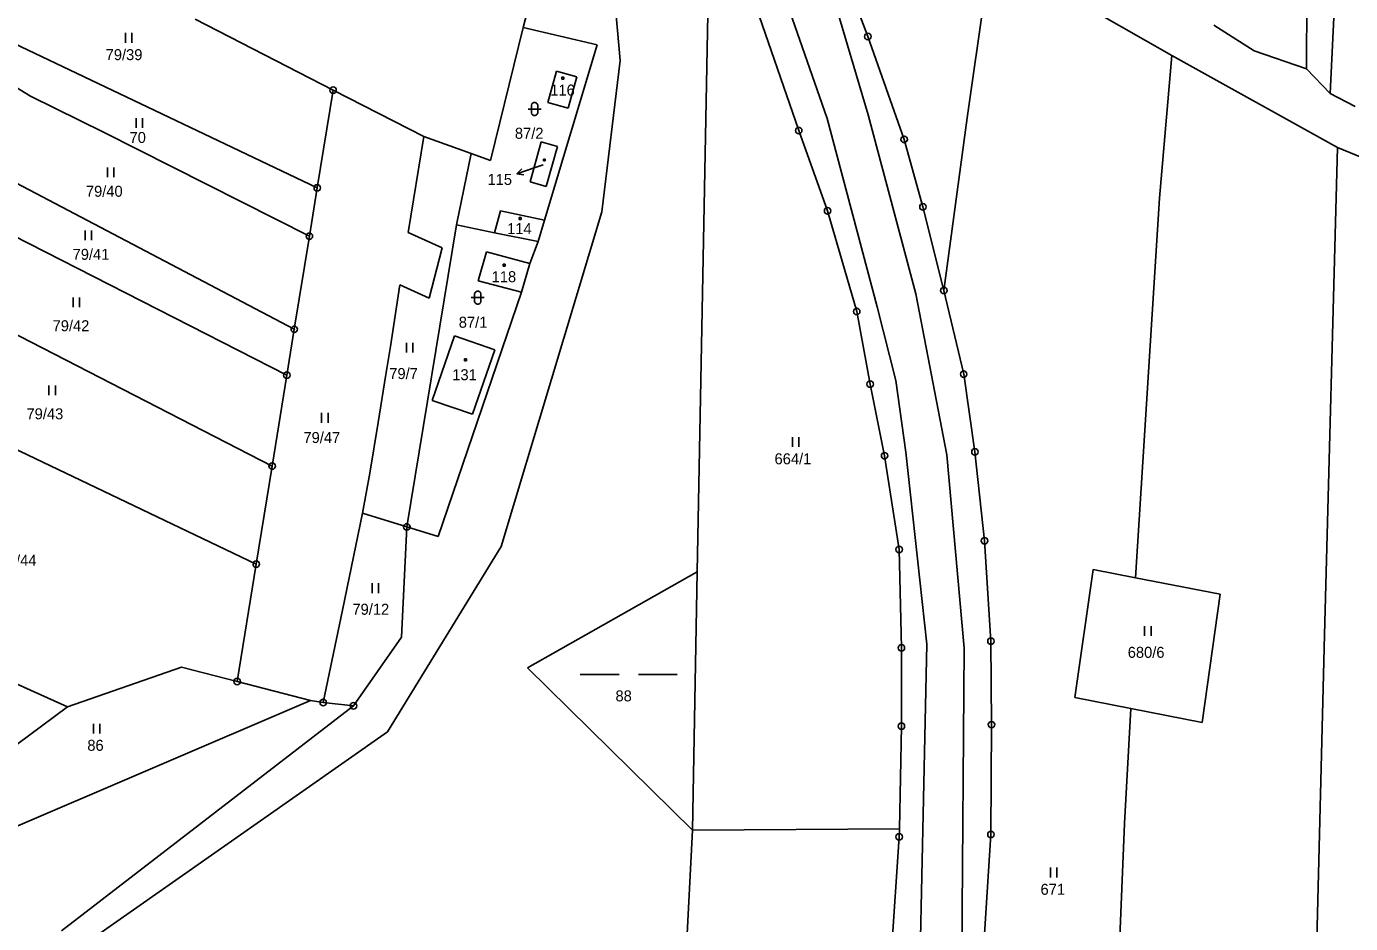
# Model space of a CAD drawing. Extents: x -794142 to -791199, y -1109267 to -1105626.
# Drawn here: x -793459.6 to -793254.8, y -1108185.5 to -1108046.6 of the extents above; entities that cross this region are included whole.
import ezdxf

# ---------------------------------------------------------------- set-up
doc = ezdxf.new("R2010")
doc.units = 0
for name, color, linetype in [('Komunikace', 7, 'Continuous'), ('Vrstva 1', 7, 'Continuous'), ('Vrstva 14', 7, 'Continuous'), ('Vrstva 15', 7, 'Continuous'), ('Vrstva 16', 7, 'Continuous'), ('Vrstva 2', 7, 'Continuous'), ('Vrstva 23', 7, 'Continuous'), ('Vrstva 25', 7, 'Continuous'), ('Vrstva 28', 7, 'Continuous')]:
    doc.layers.add(name, color=color, linetype=linetype)

msp = doc.modelspace()

# ---------------------------------------------------------------- linework, layer by layer
at = {"layer": 'Komunikace'}
msp.add_line((-793379.67, -1108068.04), (-793380.93, -1108068.48), dxfattribs=at)
at = {"layer": 'Vrstva 1'}
for p, q in [((-793257.94, -1108057.03), (-793255.37, -1108003.06)), ((-793261.46, -1108018.35), (-793261.6, -1108053.2)), ((-793353.85, -1108026.81), (-793355.86, -1108131.03)), ((-793367.78, -1108051.9), (-793369.41, -1108032.77)), ((-793310.44, -1108035.15), (-793314.07, -1108060.76)), ((-793282.44, -1108051.11), (-793310.44, -1108035.15)), ((-793332.85, -1108039.24), (-793329.45, -1108048.2)), ((-793381.6, -1108042.21), (-793382.75, -1108046.82)), ((-793479.51, -1108044.92), (-793458.99, -1108057.42)), ((-793433.49, -1108045.51), (-793412.17, -1108056.49)), ((-793346.28, -1108044.99), (-793340.14, -1108062.75)), ((-793387.84, -1108067.4), (-793382.75, -1108046.82)), ((-793371.31, -1108049.49), (-793382.75, -1108046.82)), ((-793329.45, -1108048.2), (-793323.82, -1108064.11)), ((-793275.93, -1108046.46), (-793269.7, -1108050.39)), ((-793462.7, -1108048.73), (-793414.62, -1108071.62)), ((-793379.44, -1108076.61), (-793371.31, -1108049.49)), ((-793269.7, -1108050.39), (-793261.6, -1108053.2)), ((-793370.62, -1108075.33), (-793367.78, -1108051.9)), ((-793284.33, -1108073.2), (-793282.44, -1108051.11)), ((-793282.44, -1108051.11), (-793256.81, -1108065.35)), ((-793377.6, -1108053.56), (-793378.95, -1108058.39)), ((-793377.6, -1108053.56), (-793374.46, -1108054.45)), ((-793374.46, -1108054.45), (-793375.82, -1108059.3)), ((-793261.6, -1108053.2), (-793257.94, -1108057.03)), ((-793412.17, -1108056.49), (-793414.62, -1108071.62)), ((-793412.17, -1108056.49), (-793398.15, -1108063.68)), ((-793458.99, -1108057.42), (-793447.57, -1108063.05)), ((-793375.82, -1108059.3), (-793378.95, -1108058.39)), ((-793257.94, -1108057.03), (-793254.06, -1108059.01)), ((-793481.29, -1108060.32), (-793418.17, -1108093.5)), ((-793314.07, -1108060.76), (-793317.69, -1108087.48)), ((-793447.57, -1108063.05), (-793415.84, -1108079.1)), ((-793400.56, -1108078.51), (-793398.15, -1108063.68)), ((-793398.15, -1108063.68), (-793390.82, -1108066.32)), ((-793379.96, -1108064.51), (-793381.66, -1108070.68)), ((-793379.96, -1108064.51), (-793377.47, -1108065.22)), ((-793340.14, -1108062.75), (-793335.67, -1108075.17)), ((-793323.82, -1108064.11), (-793320.92, -1108074.55)), ((-793393.1, -1108077.34), (-793390.82, -1108066.32)), ((-793390.82, -1108066.32), (-793387.84, -1108067.4)), ((-793377.47, -1108065.22), (-793379.21, -1108071.38)), ((-793256.81, -1108065.35), (-793258.79, -1108140.77)), ((-793256.81, -1108065.35), (-793242.18, -1108071.39)), ((-793419.32, -1108100.59), (-793482.23, -1108068.48)), ((-793379.21, -1108071.38), (-793381.66, -1108070.68)), ((-793414.62, -1108071.62), (-793415.84, -1108079.1)), ((-793320.92, -1108074.55), (-793317.69, -1108087.48)), ((-793288.02, -1108131.96), (-793284.33, -1108073.2)), ((-793386.26, -1108075.18), (-793387.18, -1108078.56)), ((-793379.44, -1108076.61), (-793386.26, -1108075.18)), ((-793386.16, -1108127.13), (-793370.62, -1108075.33)), ((-793380.44, -1108079.94), (-793379.44, -1108076.61)), ((-793335.67, -1108075.17), (-793331.17, -1108090.74)), ((-793400.77, -1108124.09), (-793393.1, -1108077.34)), ((-793395.3, -1108080.87), (-793400.56, -1108078.51)), ((-793387.18, -1108078.56), (-793393.1, -1108077.34)), ((-793380.44, -1108079.94), (-793387.18, -1108078.56)), ((-793415.84, -1108079.1), (-793418.17, -1108093.5)), ((-793397.32, -1108088.69), (-793395.3, -1108080.87)), ((-793381.74, -1108083.31), (-793380.44, -1108079.94)), ((-793388.43, -1108081.52), (-793389.72, -1108085.99)), ((-793381.74, -1108083.31), (-793388.43, -1108081.52)), ((-793381.74, -1108083.31), (-793383.03, -1108087.78)), ((-793403.3, -1108096.18), (-793401.87, -1108086.6)), ((-793401.87, -1108086.6), (-793397.32, -1108088.69)), ((-793383.03, -1108087.78), (-793389.72, -1108085.99)), ((-793383.03, -1108087.78), (-793395.93, -1108125.59)), ((-793317.69, -1108087.48), (-793314.62, -1108100.44)), ((-793421.6, -1108114.66), (-793468.95, -1108090.3)), ((-793331.17, -1108090.74), (-793329.09, -1108101.98)), ((-793418.17, -1108093.5), (-793419.32, -1108100.59)), ((-793393.4, -1108094.52), (-793396.84, -1108104.51)), ((-793387.17, -1108096.69), (-793393.4, -1108094.52)), ((-793404, -1108100.5), (-793403.3, -1108096.18)), ((-793390.58, -1108106.65), (-793387.17, -1108096.69)), ((-793419.32, -1108100.59), (-793421.6, -1108114.66)), ((-793404, -1108100.5), (-793405.2, -1108107.91)), ((-793314.62, -1108100.44), (-793312.88, -1108112.46)), ((-793329.09, -1108101.98), (-793326.85, -1108113.06)), ((-793396.84, -1108104.51), (-793390.58, -1108106.65)), ((-793470.04, -1108107.88), (-793424.06, -1108129.83)), ((-793405.2, -1108107.91), (-793406.48, -1108115.78)), ((-793326.85, -1108113.06), (-793324.6, -1108127.59)), ((-793312.88, -1108112.46), (-793311.39, -1108126.22)), ((-793421.6, -1108114.66), (-793424.06, -1108129.83)), ((-793407.6, -1108121.97), (-793406.48, -1108115.78)), ((-793410.71, -1108136.94), (-793407.6, -1108121.97)), ((-793407.6, -1108121.97), (-793400.77, -1108124.09)), ((-793400.77, -1108124.09), (-793401.61, -1108141.16)), ((-793400.77, -1108124.09), (-793395.93, -1108125.59)), ((-793403.74, -1108155.79), (-793386.16, -1108127.13)), ((-793324.6, -1108127.59), (-793324.25, -1108142.81)), ((-793311.39, -1108126.22), (-793310.4, -1108141.75)), ((-793424.06, -1108129.83), (-793427.01, -1108148)), ((-793355.86, -1108131.03), (-793382.1, -1108145.89)), ((-793356.57, -1108171.03), (-793355.86, -1108131.03)), ((-793294.61, -1108130.68), (-793297.41, -1108150.48)), ((-793294.61, -1108130.68), (-793288.02, -1108131.96)), ((-793288.02, -1108131.96), (-793274.95, -1108134.49)), ((-793453.28, -1108151.93), (-793494.33, -1108133.48)), ((-793274.95, -1108134.49), (-793277.71, -1108154.34)), ((-793413.69, -1108151.26), (-793410.71, -1108136.94)), ((-793401.61, -1108141.16), (-793409.01, -1108151.76)), ((-793310.4, -1108141.75), (-793310.32, -1108154.68)), ((-793258.79, -1108140.77), (-793261.5, -1108247.02)), ((-793324.25, -1108142.81), (-793324.25, -1108154.92)), ((-793435.62, -1108145.76), (-793453.28, -1108151.93)), ((-793427.01, -1108148), (-793435.62, -1108145.76)), ((-793382.1, -1108145.89), (-793356.57, -1108171.03)), ((-793415.67, -1108150.95), (-793427.01, -1108148)), ((-793297.41, -1108150.48), (-793288.76, -1108152.18)), ((-793480.52, -1108178.71), (-793415.67, -1108150.95)), ((-793453.28, -1108151.93), (-793463.11, -1108159.25)), ((-793454.16, -1108186.59), (-793409.01, -1108151.76)), ((-793415.67, -1108150.95), (-793413.69, -1108151.26)), ((-793409.01, -1108151.76), (-793413.69, -1108151.26)), ((-793289.76, -1108169.98), (-793288.76, -1108152.18)), ((-793288.76, -1108152.18), (-793277.71, -1108154.34)), ((-793310.32, -1108154.68), (-793310.4, -1108171.68)), ((-793450.61, -1108188.63), (-793403.74, -1108155.79)), ((-793324.25, -1108154.92), (-793324.57, -1108170.8)), ((-793356.57, -1108171.03), (-793362.45, -1108287.79)), ((-793356.57, -1108171.03), (-793324.57, -1108170.8)), ((-793324.57, -1108170.8), (-793324.6, -1108172.05)), ((-793291.8, -1108221.94), (-793289.76, -1108169.98)), ((-793324.6, -1108172.05), (-793325.81, -1108189.77)), ((-793310.4, -1108171.68), (-793311.56, -1108189.52))]:
    msp.add_line(p, q, dxfattribs=at)
at = {"layer": 'Vrstva 16'}
for p, q in [((-793380.93, -1108068.48), (-793383.764, -1108069.463)), ((-793383.764, -1108069.463), (-793382.983, -1108068.663)), ((-793383.764, -1108069.463), (-793382.655, -1108069.608))]:
    msp.add_line(p, q, dxfattribs=at)
at = {"layer": 'Vrstva 2'}
for p, q in [((-793329.37, -1108060.31), (-793335.41, -1108039.92)), ((-793341.9, -1108043.14), (-793335.73, -1108060.89)), ((-793322.04, -1108088.02), (-793329.37, -1108060.31)), ((-793335.73, -1108060.89), (-793328.02, -1108090.02)), ((-793317.22, -1108112.91), (-793322.04, -1108088.02)), ((-793328.02, -1108090.02), (-793325.12, -1108101.41)), ((-793325.12, -1108101.41), (-793323.58, -1108112.5)), ((-793323.58, -1108112.5), (-793320.3, -1108142.22)), ((-793314.52, -1108142.82), (-793317.22, -1108112.91)), ((-793320.3, -1108142.22), (-793322.04, -1108222.2)), ((-793314.9, -1108190.34), (-793314.52, -1108142.82))]:
    msp.add_line(p, q, dxfattribs=at)
at = {"layer": 'Vrstva 23'}
for p, q in [((-793444.29, -1108049.15), (-793444.29, -1108047.65)), ((-793443.29, -1108047.65), (-793443.29, -1108049.15)), ((-793381.4, -1108058.62), (-793381.3, -1108058.52)), ((-793381.3, -1108058.52), (-793381.1, -1108058.42)), ((-793381.1, -1108058.42), (-793380.9, -1108058.42)), ((-793380.9, -1108058.42), (-793380.7, -1108058.52)), ((-793380.7, -1108058.52), (-793380.6, -1108058.62)), ((-793382, -1108059.42), (-793380, -1108059.42)), ((-793381.5, -1108058.82), (-793381.4, -1108058.62)), ((-793381.5, -1108060.02), (-793381.5, -1108058.82)), ((-793381.4, -1108060.22), (-793381.5, -1108060.02)), ((-793381.3, -1108060.32), (-793381.4, -1108060.22)), ((-793381.1, -1108060.42), (-793381.3, -1108060.32)), ((-793380.9, -1108060.42), (-793381.1, -1108060.42)), ((-793380.7, -1108060.32), (-793380.9, -1108060.42)), ((-793380.6, -1108060.22), (-793380.7, -1108060.32)), ((-793380.6, -1108058.62), (-793380.5, -1108058.82)), ((-793380.5, -1108060.02), (-793380.6, -1108060.22)), ((-793380.5, -1108058.82), (-793380.5, -1108060.02)), ((-793442.66, -1108062.34), (-793442.66, -1108060.84)), ((-793441.66, -1108060.84), (-793441.66, -1108062.34)), ((-793447.09, -1108069.98), (-793447.09, -1108068.48)), ((-793446.09, -1108068.48), (-793446.09, -1108069.98)), ((-793450.54, -1108079.73), (-793450.54, -1108078.23)), ((-793449.54, -1108078.23), (-793449.54, -1108079.73)), ((-793452.4, -1108090.07), (-793452.4, -1108088.57)), ((-793451.4, -1108088.57), (-793451.4, -1108090.07)), ((-793390.79, -1108088.6), (-793388.79, -1108088.6)), ((-793390.29, -1108088), (-793390.19, -1108087.8)), ((-793390.29, -1108089.2), (-793390.29, -1108088)), ((-793390.19, -1108089.4), (-793390.29, -1108089.2)), ((-793390.19, -1108087.8), (-793390.09, -1108087.7)), ((-793390.09, -1108087.7), (-793389.89, -1108087.6)), ((-793389.89, -1108087.6), (-793389.69, -1108087.6)), ((-793389.69, -1108087.6), (-793389.49, -1108087.7)), ((-793389.49, -1108087.7), (-793389.39, -1108087.8)), ((-793389.39, -1108087.8), (-793389.29, -1108088)), ((-793389.29, -1108089.2), (-793389.39, -1108089.4)), ((-793389.29, -1108088), (-793389.29, -1108089.2)), ((-793390.09, -1108089.5), (-793390.19, -1108089.4)), ((-793389.89, -1108089.6), (-793390.09, -1108089.5)), ((-793389.69, -1108089.6), (-793389.89, -1108089.6)), ((-793389.49, -1108089.5), (-793389.69, -1108089.6)), ((-793389.39, -1108089.4), (-793389.49, -1108089.5)), ((-793400.82, -1108097.09), (-793400.82, -1108095.59)), ((-793399.82, -1108095.59), (-793399.82, -1108097.09)), ((-793456.13, -1108103.7), (-793456.13, -1108102.2)), ((-793455.13, -1108102.2), (-793455.13, -1108103.7)), ((-793413.95, -1108107.95), (-793413.95, -1108106.45)), ((-793412.95, -1108106.45), (-793412.95, -1108107.95)), ((-793341.12, -1108111.69), (-793341.12, -1108110.19)), ((-793340.12, -1108110.19), (-793340.12, -1108111.69)), ((-793406.12, -1108134.31), (-793406.12, -1108132.81)), ((-793405.12, -1108132.81), (-793405.12, -1108134.31)), ((-793286.63, -1108140.95), (-793286.63, -1108139.45)), ((-793285.63, -1108139.45), (-793285.63, -1108140.95)), ((-793373.94, -1108146.91), (-793367.94, -1108146.91)), ((-793364.94, -1108146.91), (-793358.94, -1108146.91)), ((-793449.23, -1108156.03), (-793449.23, -1108154.53)), ((-793448.23, -1108154.53), (-793448.23, -1108156.03)), ((-793301.2, -1108178.31), (-793301.2, -1108176.81)), ((-793300.2, -1108176.81), (-793300.2, -1108178.31))]:
    msp.add_line(p, q, dxfattribs=at)
at = {"layer": 'Vrstva 25'}
for p, q in [((-793376.79, -1108054.47), (-793376.49, -1108054.47)), ((-793376.79, -1108054.77), (-793376.79, -1108054.47)), ((-793376.49, -1108054.47), (-793376.49, -1108054.77)), ((-793376.49, -1108054.77), (-793376.79, -1108054.77)), ((-793379.64, -1108067.15), (-793379.34, -1108067.15)), ((-793379.64, -1108067.45), (-793379.64, -1108067.15)), ((-793379.34, -1108067.45), (-793379.64, -1108067.45)), ((-793379.34, -1108067.15), (-793379.34, -1108067.45)), ((-793383.38, -1108076.21), (-793383.08, -1108076.21)), ((-793383.38, -1108076.51), (-793383.38, -1108076.21)), ((-793383.08, -1108076.51), (-793383.38, -1108076.51)), ((-793383.08, -1108076.21), (-793383.08, -1108076.51)), ((-793385.84, -1108083.44), (-793385.54, -1108083.44)), ((-793385.84, -1108083.74), (-793385.84, -1108083.44)), ((-793385.54, -1108083.74), (-793385.84, -1108083.74)), ((-793385.54, -1108083.44), (-793385.54, -1108083.74)), ((-793391.84, -1108098.07), (-793391.54, -1108098.07)), ((-793391.84, -1108098.37), (-793391.84, -1108098.07)), ((-793391.54, -1108098.37), (-793391.84, -1108098.37)), ((-793391.54, -1108098.07), (-793391.54, -1108098.37))]:
    msp.add_line(p, q, dxfattribs=at)
at = {"layer": 'Vrstva 28'}
for centre, radius in [((-793329.45, -1108048.2), 0.5), ((-793329.45, -1108048.2), 0.01), ((-793412.17, -1108056.49), 0.5), ((-793412.17, -1108056.49), 0.01), ((-793340.14, -1108062.75), 0.5), ((-793340.14, -1108062.75), 0.01), ((-793323.82, -1108064.11), 0.5), ((-793323.82, -1108064.11), 0.01), ((-793414.62, -1108071.62), 0.5), ((-793414.62, -1108071.62), 0.01), ((-793335.67, -1108075.17), 0.5), ((-793320.92, -1108074.55), 0.5), ((-793320.92, -1108074.55), 0.01), ((-793335.67, -1108075.17), 0.01), ((-793415.84, -1108079.1), 0.5), ((-793415.84, -1108079.1), 0.01), ((-793317.69, -1108087.48), 0.5), ((-793317.69, -1108087.48), 0.01), ((-793331.17, -1108090.74), 0.5), ((-793331.17, -1108090.74), 0.01), ((-793418.17, -1108093.5), 0.5), ((-793418.17, -1108093.5), 0.01), ((-793419.32, -1108100.59), 0.5), ((-793419.32, -1108100.59), 0.01), ((-793329.09, -1108101.98), 0.5), ((-793314.62, -1108100.44), 0.5), ((-793314.62, -1108100.44), 0.01), ((-793329.09, -1108101.98), 0.01), ((-793326.85, -1108113.06), 0.5), ((-793326.85, -1108113.06), 0.01), ((-793312.88, -1108112.46), 0.5), ((-793312.88, -1108112.46), 0.01), ((-793421.6, -1108114.66), 0.5), ((-793421.6, -1108114.66), 0.01), ((-793400.77, -1108124.09), 0.5), ((-793400.77, -1108124.09), 0.01), ((-793311.39, -1108126.22), 0.5), ((-793324.6, -1108127.59), 0.5), ((-793324.6, -1108127.59), 0.01), ((-793311.39, -1108126.22), 0.01), ((-793424.06, -1108129.83), 0.5), ((-793424.06, -1108129.83), 0.01), ((-793324.25, -1108142.81), 0.5), ((-793310.4, -1108141.75), 0.5), ((-793310.4, -1108141.75), 0.01), ((-793324.25, -1108142.81), 0.01), ((-793427.01, -1108148), 0.5), ((-793427.01, -1108148), 0.01), ((-793413.69, -1108151.26), 0.5), ((-793413.69, -1108151.26), 0.01), ((-793409.01, -1108151.76), 0.5), ((-793409.01, -1108151.76), 0.01), ((-793324.25, -1108154.92), 0.5), ((-793310.32, -1108154.68), 0.5), ((-793310.32, -1108154.68), 0.01), ((-793324.25, -1108154.92), 0.01), ((-793310.4, -1108171.68), 0.5), ((-793324.6, -1108172.05), 0.5), ((-793324.6, -1108172.05), 0.01), ((-793310.4, -1108171.68), 0.01)]:
    msp.add_circle(centre, radius, dxfattribs=at)

# ---------------------------------------------------------------- texts
at = {"layer": 'Vrstva 14'}
for s, p in [('79/39', (-793447.357, -1108051.85)), ('87/2', (-793384.046, -1108064.02)), ('70', (-793443.663, -1108064.67)), ('79/40', (-793450.412, -1108072.99)), ('79/41', (-793452.466, -1108082.75)), ('79/42', (-793455.562, -1108093.8)), ('87/1', (-793392.73, -1108093.26)), ('79/7', (-793403.483, -1108101.2)), ('79/43', (-793459.602, -1108107.43)), ('79/47', (-793416.759, -1108111.1)), ('664/1', (-793343.879, -1108114.39)), ('79/44', (-793463.738, -1108130.1)), ('79/12', (-793409.18, -1108137.67)), ('680/6', (-793289.24, -1108144.34)), ('88', (-793368.486, -1108151.08)), ('86', (-793450.187, -1108158.73)), ('671', (-793302.727, -1108181.01))]:
    msp.add_text(s, height=1.7, dxfattribs=at).set_placement(p)
at = {"layer": 'Vrstva 15'}
for s, height, p in [('116', 1.7, (-793378.573, -1108057.33)), ('115', 0.1, (-793379.773, -1108068.04)), ('114', 1.7, (-793385.249, -1108078.77)), ('118', 1.7, (-793387.643, -1108086.21)), ('131', 1.7, (-793393.733, -1108101.38))]:
    msp.add_text(s, height=height, dxfattribs=at).set_placement(p)
at = {"layer": 'Vrstva 16'}
msp.add_text('115', height=1.7, dxfattribs=at).set_placement((-793388.279, -1108071.16))

doc.saveas('drawing.dxf')
